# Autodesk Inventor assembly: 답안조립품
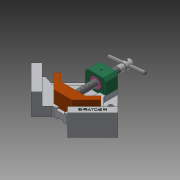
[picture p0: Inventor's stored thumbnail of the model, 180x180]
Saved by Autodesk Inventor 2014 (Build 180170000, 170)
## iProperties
Created: 2019-04
Part Number: 답안조립품
Document SubType Name: Assembly
Designer: kb542-22
Author: kb542-22
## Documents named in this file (11)
- C:\Users\kb542-22\Desktop\490407V1006\답안조립품.iam
- C:\Users\kb542-22\Desktop\490407V1006\리드스크류.ipt
- C:\Users\kb542-22\Desktop\490407V1006\멈춤나사 M4x5.ipt
- C:\Users\kb542-22\Desktop\490407V1006\멈춤나사 M4x10.ipt
- C:\Users\kb542-22\Desktop\490407V1006\베이스.ipt
- C:\Users\kb542-22\Desktop\490407V1006\볼트 M4x16.ipt
- C:\Users\kb542-22\Desktop\490407V1006\부시.ipt
- C:\Users\kb542-22\Desktop\490407V1006\서포트.ipt
- C:\Users\kb542-22\Desktop\490407V1006\조.ipt
- C:\Users\kb542-22\Desktop\490407V1006\평행 핀 2.5x24.ipt
- C:\Users\kb542-22\Desktop\490407V1006\핸들.ipt
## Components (1 placed, 1 different names)
1. 핸들:1
